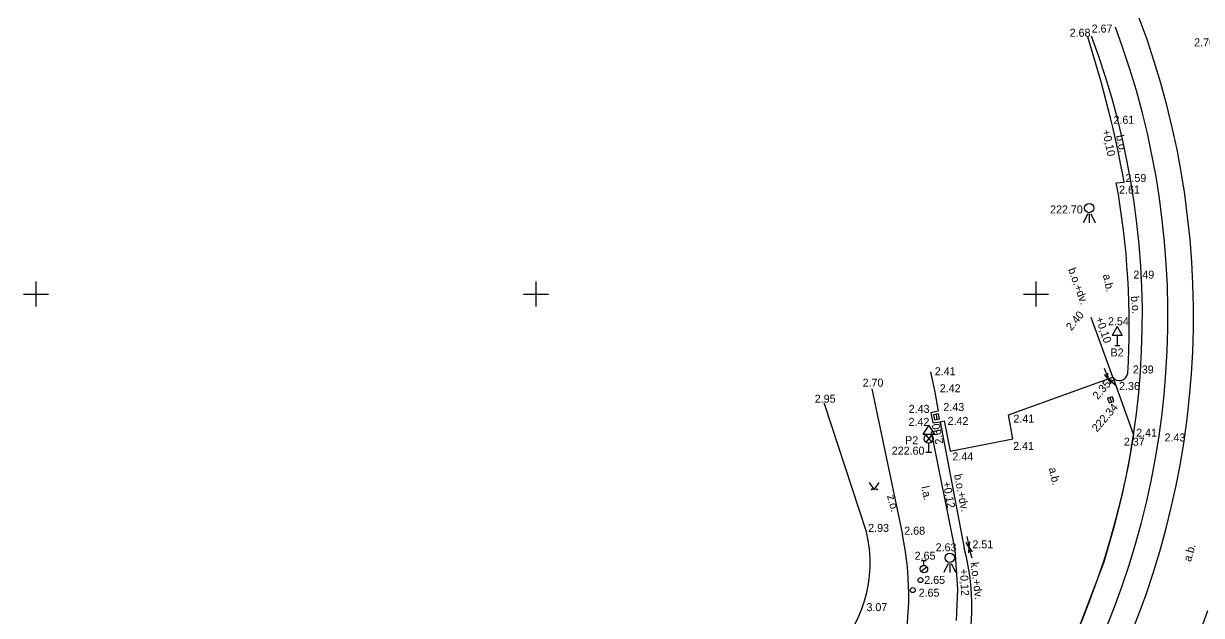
# Model space of a CAD drawing. Extents: x -598741 to -598592, y -1156973 to -1156763.
# Drawn here: x -598700.6 to -598641.7, y -1156866.1 to -1156836.5 of the extents above; entities that cross this region are included whole.
import ezdxf

# ---------------------------------------------------------------- set-up
doc = ezdxf.new("R2010")
doc.units = 0
for name, color, linetype in [('Vrstva 10', 7, 'Continuous'), ('Vrstva 13', 7, 'Continuous'), ('Vrstva 14', 7, 'Continuous'), ('Vrstva 19', 7, 'Continuous'), ('Vrstva 24', 7, 'Continuous'), ('Vrstva 25', 7, 'Continuous'), ('Vrstva 44', 7, 'Continuous'), ('Vrstva 49', 7, 'Continuous'), ('Vrstva 50', 7, 'Continuous'), ('Vrstva 58', 7, 'Continuous'), ('Vrstva 62', 7, 'Continuous'), ('Vrstva 63', 7, 'Continuous'), ('Vrstva 7', 7, 'Continuous')]:
    doc.layers.add(name, color=color, linetype=linetype)

msp = doc.modelspace()

# ---------------------------------------------------------------- linework, layer by layer
at = {"layer": 'Vrstva 10'}
msp.add_line((-598658.48, -1156861.89), (-598660.6, -1156855.43), dxfattribs=at)
msp.add_arc((-598664.846, -1156863.438), 6.551, 312.7345, 13.66876, dxfattribs=at)
at = {"layer": 'Vrstva 13'}
for centre, radius, start, end in [((-598684.3, -1156851.077), 42.168, 331.38228, 20.65336), ((-598684.475, -1156851.099), 39.789, 331.38593, 20.59112), ((-598673.908, -1156854.609), 34.374, 299.14988, 340.96763)]:
    msp.add_arc(centre, radius, start, end, dxfattribs=at)
at = {"layer": 'Vrstva 14'}
msp.add_lwpolyline([(-598658.34, -1156859.415), (-598658.09, -1156859.79), (-598657.84, -1156859.415)], dxfattribs=at)
for centre in [(-598658.215, -1156859.765), (-598657.965, -1156859.765)]:
    msp.add_circle(centre, 0.025, dxfattribs=at)
at = {"layer": 'Vrstva 19'}
for p, q in [((-598645.94, -1156851.62), (-598646.19, -1156852.07)), ((-598645.69, -1156852.07), (-598646.19, -1156852.07)), ((-598645.94, -1156851.62), (-598645.69, -1156852.07)), ((-598645.94, -1156852.07), (-598645.94, -1156852.57)), ((-598646.065, -1156852.57), (-598645.815, -1156852.57))]:
    msp.add_line(p, q, dxfattribs=at)
msp.add_arc((-598684.388, -1156851.088), 40.979, 331.38299, 20.62273, dxfattribs=at)
at = {"layer": 'Vrstva 24'}
for p, q in [((-598655.757, -1156863.866), (-598655.462, -1156863.634)), ((-598655.735, -1156863.312), (-598655.485, -1156863.312)), ((-598655.61, -1156863.562), (-598655.61, -1156863.312))]:
    msp.add_line(p, q, dxfattribs=at)
for centre, radius in [((-598655.61, -1156863.75), 0.188), ((-598655.78, -1156864.3), 0.125), ((-598656.17, -1156864.8), 0.125)]:
    msp.add_circle(centre, radius, dxfattribs=at)
at = {"layer": 'Vrstva 25'}
for p, q in [((-598646.306, -1156855.17), (-598646.234, -1156855.41)), ((-598655.003, -1156856.017), (-598654.957, -1156856.263))]:
    msp.add_line(p, q, dxfattribs=at)
for points in [[(-598646.427, -1156855.207), (-598646.354, -1156855.446), (-598646.114, -1156855.374), (-598646.186, -1156855.134)], [(-598655.127, -1156856.041), (-598655.08, -1156856.286), (-598654.834, -1156856.239), (-598654.881, -1156855.994)]]:
    msp.add_lwpolyline(points, close=True, dxfattribs=at)
at = {"layer": 'Vrstva 44'}
for p, q in [((-598647.414, -1156845.993), (-598647.64, -1156846.445)), ((-598647.34, -1156845.995), (-598647.34, -1156846.445)), ((-598647.265, -1156845.993), (-598647.04, -1156846.445)), ((-598655.22, -1156857.06), (-598655.52, -1156857.404)), ((-598655.52, -1156857.06), (-598655.22, -1156857.404)), ((-598655.52, -1156857.91), (-598655.22, -1156857.91)), ((-598655.37, -1156857.91), (-598655.37, -1156857.46)), ((-598654.394, -1156863.473), (-598654.62, -1156863.925)), ((-598654.32, -1156863.475), (-598654.32, -1156863.925)), ((-598654.245, -1156863.473), (-598654.02, -1156863.925))]:
    msp.add_line(p, q, dxfattribs=at)
msp.add_lwpolyline([(-598655.67, -1156857.004), (-598655.07, -1156857.004), (-598655.37, -1156856.554), (-598655.67, -1156857.004)], dxfattribs=at)
for centre, radius in [((-598647.34, -1156845.7), 0.234), ((-598655.37, -1156857.232), 0.228), ((-598654.32, -1156863.18), 0.234)]:
    msp.add_circle(centre, radius, dxfattribs=at)
at = {"layer": 'Vrstva 49'}
for p, q in [((-598646.603, -1156853.711), (-598646.401, -1156854.238)), ((-598646.401, -1156854.238), (-598646.588, -1156854.026)), ((-598646.401, -1156854.238), (-598646.409, -1156853.955)), ((-598645.986, -1156854.607), (-598646.409, -1156854.235)), ((-598646.409, -1156854.235), (-598646.272, -1156854.481)), ((-598646.409, -1156854.235), (-598646.146, -1156854.336)), ((-598653.351, -1156862.667), (-598653.501, -1156862.427)), ((-598653.465, -1156862.115), (-598653.351, -1156862.667)), ((-598653.358, -1156862.661), (-598653.372, -1156862.943)), ((-598653.198, -1156863.202), (-598653.358, -1156862.661)), ((-598653.358, -1156862.661), (-598653.189, -1156862.887)), ((-598653.351, -1156862.667), (-598653.313, -1156862.387))]:
    msp.add_line(p, q, dxfattribs=at)
at = {"layer": 'Vrstva 62'}
for p, q in [((-598700, -1156850.625), (-598700, -1156849.375)), ((-598675, -1156850.625), (-598675, -1156849.375)), ((-598650, -1156850.625), (-598650, -1156849.375)), ((-598700.625, -1156850), (-598699.375, -1156850)), ((-598675.625, -1156850), (-598674.375, -1156850)), ((-598650.625, -1156850), (-598649.375, -1156850))]:
    msp.add_line(p, q, dxfattribs=at)
at = {"layer": 'Vrstva 63'}
msp.add_lwpolyline([(-598653.98, -1156866.32), (-598653.91, -1156864.76), (-598654.05, -1156862.78), (-598655.23, -1156856.88), (-598654.715, -1156856.779), (-598654.79, -1156856.38), (-598654.593, -1156856.343), (-598654.29, -1156857.85), (-598651.17, -1156857.23), (-598651.38, -1156856.03), (-598646.17, -1156854.15), (-598645.13, -1156857.04), (-598645.4, -1156858.59), (-598645.73, -1156860.14), (-598646.11, -1156861.65), (-598646.62, -1156863.4), (-598647.88, -1156866.71)], dxfattribs=at)
at = {"layer": 'Vrstva 7'}
for p, q in [((-598645.99, -1156844.44), (-598645.6, -1156844.4)), ((-598646.17, -1156854.15), (-598647.25, -1156851.17)), ((-598658.21, -1156854.74), (-598656.68, -1156862.03))]:
    msp.add_line(p, q, dxfattribs=at)
msp.add_lwpolyline([(-598655.28, -1156853.89), (-598655.07, -1156854.91), (-598654.89, -1156855.85), (-598655.26, -1156855.94), (-598655.17, -1156856.43), (-598654.79, -1156856.38), (-598653.6, -1156862.71)], dxfattribs=at)
for centre, radius, start, end in [((-598701.722, -1156854.635), 57.047, 10.33558, 17.84845), ((-598684.763, -1156851.541), 39.418, 356.46724, 10.37845), ((-598645.831, -1156853.911), 0.415, 215.14485, 351.84661), ((-598670.914, -1156865.033), 14.547, 348.47374, 11.91405), ((-598664.394, -1156865.64), 11.185, 301.56073, 15.18571)]:
    msp.add_arc(centre, radius, start, end, dxfattribs=at)

# ---------------------------------------------------------------- texts
at = {"layer": 'Vrstva 49'}
for s, rotation, p in [('b.o.', 281.73352, (-598646.008, -1156842.089)), ('b.o.+dv.', 290.01079, (-598648.41, -1156848.77)), ('a.b.', 282.03892, (-598646.665, -1156849.05)), ('b.o.', 274.5092, (-598645.256, -1156850.113)), ('b.o.+dv.', 281.03817, (-598654.104, -1156859.038)), ('a.b.', 282.37216, (-598649.367, -1156858.712)), ('l.a.', 282.03892, (-598655.742, -1156859.637)), ('z.o.', 284.78445, (-598657.457, -1156860.09)), ('a.b.', 73.68615, (-598642.265, -1156863.408)), ('k.o.+dv.', 277.11226, (-598653.282, -1156863.428))]:
    msp.add_text(s, height=0.4, rotation=rotation, dxfattribs=at).set_placement(p)
for s, p in [('B2', (-598646.278, -1156853.12)), ('P2', (-598656.55, -1156857.51))]:
    msp.add_text(s, height=0.4, dxfattribs=at).set_placement(p)
at = {"layer": 'Vrstva 50'}
for s, rotation, p in [('+0,10', 282.14151, (-598646.699, -1156841.822)), ('+0,10', 289.08096, (-598647.034, -1156851.215)), ('+0,12', 280.22301, (-598654.671, -1156859.406)), ('+0,12', 273.00297, (-598653.812, -1156863.748))]:
    msp.add_text(s, height=0.4, rotation=rotation, dxfattribs=at).set_placement(p)
at = {"layer": 'Vrstva 58'}
for s, p in [('2.68', (-598648.323, -1156837.14)), ('2.67', (-598647.223, -1156836.93)), ('2.70', (-598642.096, -1156837.62)), ('2.61', (-598646.132, -1156841.49)), ('2.59', (-598645.531, -1156844.4)), ('2.61', (-598645.852, -1156844.98)), ('222.70', (-598649.302, -1156845.97)), ('2.49', (-598645.136, -1156849.23)), ('2.54', (-598646.406, -1156851.56)), ('2.41', (-598655.066, -1156854.06)), ('2.39', (-598645.162, -1156853.97)), ('2.70', (-598658.676, -1156854.63)), ('2.36', (-598645.852, -1156854.8)), ('2.95', (-598661.066, -1156855.43)), ('2.42', (-598654.816, -1156854.91)), ('2.43', (-598656.37, -1156855.94)), ('2.43', (-598654.636, -1156855.85)), ('2.42', (-598656.376, -1156856.59)), ('2.42', (-598654.426, -1156856.54)), ('2.41', (-598651.136, -1156856.43)), ('2.41', (-598644.996, -1156857.13)), ('2.41', (-598651.146, -1156857.79)), ('2.37', (-598645.612, -1156857.58)), ('2.43', (-598643.576, -1156857.37)), ('222.60', (-598657.218, -1156858.03)), ('2.44', (-598654.186, -1156858.32)), ('2.93', (-598658.396, -1156861.89)), ('2.68', (-598656.593, -1156862.03)), ('2.63', (-598655.023, -1156862.86)), ('2.51', (-598653.186, -1156862.71)), ('2.65', (-598656.073, -1156863.28)), ('2.65', (-598655.593, -1156864.49)), ('2.65', (-598655.873, -1156865.13)), ('3.07', (-598658.482, -1156865.85))]:
    msp.add_text(s, height=0.4, dxfattribs=at).set_placement(p)
for s, rotation, p in [('2.40', 51.04409, (-598648.235, -1156851.863)), ('2.35', 49.17298, (-598646.916, -1156855.304)), ('222.34', 49.10672, (-598646.955, -1156856.923)), ('2.60', 100.68491, (-598654.637, -1156857.464))]:
    msp.add_text(s, height=0.4, rotation=rotation, dxfattribs=at).set_placement(p)

doc.saveas('drawing.dxf')
